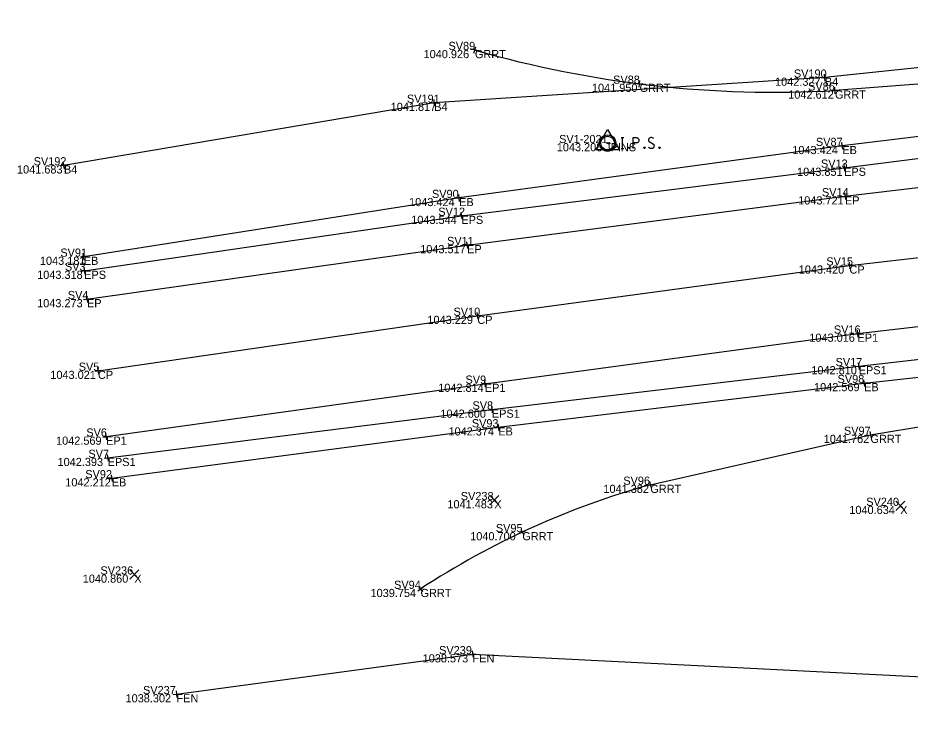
# Model space of a CAD drawing. Extents: x 1542529 to 1609210, y 587215 to 645373.
# Drawn here: x 1608659.8 to 1608791, y 645167.7 to 645271.5 of the extents above; entities that cross this region are included whole.
import ezdxf

# ---------------------------------------------------------------- set-up
doc = ezdxf.new("R2010")
doc.units = 0
for name, color, linetype in [('PV_X_COP', 7, 'Continuous'), ('PV_X_EOP', 7, 'Continuous'), ('PV_X_Shoulder', 7, 'Continuous'), ('PV_X_Shoulder_Aggregate', 7, 'Continuous'), ('RD_X_Fence', 7, 'Continuous'), ('RD_X_GR_Rt', 7, 'Continuous'), ('SV_Control_Point', 7, 'Continuous'), ('SV_P_Mon_Cells_Set', 7, 'Continuous'), ('SV_X_Break_Lines', 7, 'Continuous'), ('SV_X_Random_Point', 7, 'Continuous'), ('SV_X_Shot_Marker', 7, 'Continuous'), ('SV_X_Text_Comment', 7, 'Continuous'), ('SV_X_Text_Elevation', 7, 'Continuous'), ('SV_X_Text_Name', 7, 'Continuous')]:
    doc.layers.add(name, color=color, linetype=linetype)

msp = doc.modelspace()

# ---------------------------------------------------------------- linework, layer by layer
at = {"layer": 'PV_X_COP'}
msp.add_lwpolyline([(1608671.55, 645219.6), (1608727.32, 645227.68), (1608782.03, 645235.07), (1608837.47, 645241.45), (1608884.55, 645247.04)], dxfattribs=at)
at = {"layer": 'PV_X_EOP'}
for points in [[(1608669.93, 645230.13), (1608725.82, 645238.07), (1608781.37, 645245.23), (1608836.27, 645251.75), (1608887.49, 645257.66)], [(1608672.74, 645209.93), (1608728.42, 645217.7), (1608783.22, 645225.06), (1608838.86, 645231.47), (1608881.41, 645236.41)]]:
    msp.add_lwpolyline(points, dxfattribs=at)
at = {"layer": 'PV_X_Shoulder'}
for points in [[(1608669.52, 645234.3), (1608724.97, 645242.37), (1608781.24, 645249.44), (1608835.57, 645256.3), (1608888.53, 645262.28)], [(1608672.97, 645206.8), (1608729.46, 645213.9), (1608783.39, 645220.28), (1608840.72, 645226.83), (1608879.25, 645231.61)]]:
    msp.add_lwpolyline(points, dxfattribs=at)
at = {"layer": 'PV_X_Shoulder_Aggregate'}
for points in [[(1608884.62, 645267.54), (1608835.11, 645259.22), (1608780.98, 645252.63), (1608724.64, 645244.99), (1608669.45, 645236.36)], [(1608673.57, 645203.81), (1608730.4, 645211.29), (1608784.18, 645217.8), (1608839.95, 645223.89), (1608878.18, 645228.32)]]:
    msp.add_lwpolyline(points, dxfattribs=at)
at = {"layer": 'RD_X_Fence'}
msp.add_lwpolyline([(1608683.09, 645172.08), (1608726.62, 645177.95), (1608798.6, 645174.35), (1608837.85, 645170.02), (1608869.08, 645167.68)], dxfattribs=at)
at = {"layer": 'RD_X_GR_Rt'}
for p, q in [((1608834.71, 645264.92), (1608779.9, 645260.78)), ((1608785.12, 645210.19), (1608840.67, 645219.49)), ((1608752.75, 645202.85), (1608785.12, 645210.19))]:
    msp.add_line(p, q, dxfattribs=at)
for centre, radius, start, end in [((1608771, 645420.11), 159.58, 253.98, 273.1961), ((1608785.29, 645086.07), 121.23, 105.5726, 123.169)]:
    msp.add_arc(centre, radius, start, end, dxfattribs=at)
at = {"layer": 'SV_Control_Point'}
for p, q in [((1608744.74, 645252.05), (1608746.47, 645255.05)), ((1608746.47, 645255.05), (1608748.21, 645252.05)), ((1608746.47, 645253.05), (1608746.47, 645253.05)), ((1608748.21, 645252.05), (1608744.74, 645252.05))]:
    msp.add_line(p, q, dxfattribs=at)
msp.add_circle((1608746.47, 645253.05), 1, dxfattribs=at)
at = {"layer": 'SV_P_Mon_Cells_Set'}
for points in [[(1608746.57, 645253.09), (1608746.59, 645253.09)], [(1608746.57, 645253.01), (1608746.59, 645253.01)], [(1608746.58, 645253.01), (1608746.58, 645253.09)], [(1608746.63, 645253.02), (1608746.63, 645253.02), (1608746.64, 645253.02), (1608746.64, 645253.02), (1608746.64, 645253.02), (1608746.64, 645253.01), (1608746.63, 645253.01), (1608746.63, 645253.01), (1608746.63, 645253.01), (1608746.63, 645253.02), (1608746.63, 645253.02), (1608746.63, 645253.02), (1608746.63, 645253.02)], [(1608746.66, 645253.01), (1608746.66, 645253.09), (1608746.69, 645253.09), (1608746.69, 645253.09), (1608746.69, 645253.09), (1608746.7, 645253.09), (1608746.7, 645253.09), (1608746.7, 645253.08), (1608746.7, 645253.08), (1608746.7, 645253.08), (1608746.7, 645253.07), (1608746.7, 645253.07), (1608746.7, 645253.06), (1608746.7, 645253.06), (1608746.7, 645253.06), (1608746.69, 645253.05), (1608746.69, 645253.05), (1608746.69, 645253.05), (1608746.66, 645253.05)], [(1608746.74, 645253.02), (1608746.75, 645253.02), (1608746.75, 645253.02), (1608746.75, 645253.02), (1608746.75, 645253.02), (1608746.75, 645253.01), (1608746.75, 645253.01), (1608746.74, 645253.01), (1608746.74, 645253.01), (1608746.74, 645253.02), (1608746.74, 645253.02), (1608746.74, 645253.02), (1608746.74, 645253.02)], [(1608746.81, 645253.09), (1608746.81, 645253.09), (1608746.81, 645253.09), (1608746.8, 645253.09), (1608746.8, 645253.09), (1608746.79, 645253.09), (1608746.79, 645253.09), (1608746.78, 645253.09), (1608746.78, 645253.09), (1608746.77, 645253.08), (1608746.77, 645253.08), (1608746.77, 645253.07), (1608746.77, 645253.07), (1608746.78, 645253.06), (1608746.81, 645253.04), (1608746.81, 645253.04), (1608746.81, 645253.04), (1608746.81, 645253.04), (1608746.81, 645253.03), (1608746.81, 645253.03), (1608746.81, 645253.03), (1608746.81, 645253.02), (1608746.81, 645253.02), (1608746.81, 645253.02), (1608746.81, 645253.02), (1608746.81, 645253.01), (1608746.8, 645253.01), (1608746.8, 645253.01), (1608746.8, 645253.01), (1608746.79, 645253.01), (1608746.79, 645253.01), (1608746.78, 645253.02), (1608746.77, 645253.02)], [(1608746.85, 645253.02), (1608746.86, 645253.02), (1608746.86, 645253.02), (1608746.86, 645253.02), (1608746.86, 645253.02), (1608746.86, 645253.01), (1608746.86, 645253.01), (1608746.85, 645253.01), (1608746.85, 645253.01), (1608746.85, 645253.02), (1608746.85, 645253.02), (1608746.85, 645253.02), (1608746.85, 645253.02)], [(1608748.49, 645253.85), (1608748.84, 645253.85)], [(1608748.67, 645252.25), (1608748.67, 645253.85)], [(1608750.23, 645252.25), (1608750.23, 645253.85), (1608750.76, 645253.85), (1608750.82, 645253.84), (1608750.89, 645253.82), (1608750.93, 645253.79), (1608750.96, 645253.77), (1608751.01, 645253.7), (1608751.04, 645253.64), (1608751.06, 645253.54), (1608751.06, 645253.39), (1608751.05, 645253.34), (1608751.03, 645253.26), (1608750.98, 645253.17), (1608750.94, 645253.14), (1608750.91, 645253.11), (1608750.85, 645253.09), (1608750.76, 645253.07), (1608750.23, 645253.07)], [(1608753.24, 645253.74), (1608753.22, 645253.77), (1608753.19, 645253.79), (1608753.09, 645253.83), (1608752.97, 645253.85), (1608752.88, 645253.85), (1608752.85, 645253.85), (1608752.7, 645253.82), (1608752.58, 645253.74), (1608752.5, 645253.64), (1608752.48, 645253.54), (1608752.48, 645253.46), (1608752.5, 645253.36), (1608752.59, 645253.27), (1608753.2, 645252.9), (1608753.25, 645252.85), (1608753.28, 645252.8), (1608753.3, 645252.72), (1608753.3, 645252.64), (1608753.29, 645252.57), (1608753.28, 645252.52), (1608753.25, 645252.46), (1608753.23, 645252.4), (1608753.21, 645252.37), (1608753.18, 645252.33), (1608753.14, 645252.3), (1608753.1, 645252.28), (1608753.07, 645252.27), (1608752.97, 645252.25), (1608752.81, 645252.25), (1608752.71, 645252.28), (1608752.57, 645252.37), (1608752.48, 645252.44)], [(1608748.49, 645252.25), (1608748.84, 645252.25)], [(1608749.63, 645252.47), (1608749.68, 645252.47), (1608749.72, 645252.44), (1608749.75, 645252.39), (1608749.75, 645252.33), (1608749.72, 645252.28), (1608749.68, 645252.25), (1608749.63, 645252.25), (1608749.59, 645252.28), (1608749.56, 645252.33), (1608749.56, 645252.39), (1608749.59, 645252.44), (1608749.63, 645252.47)], [(1608751.88, 645252.47), (1608751.93, 645252.47), (1608751.96, 645252.44), (1608752, 645252.39), (1608752, 645252.33), (1608751.96, 645252.28), (1608751.93, 645252.25), (1608751.88, 645252.25), (1608751.84, 645252.28), (1608751.81, 645252.33), (1608751.81, 645252.39), (1608751.84, 645252.44), (1608751.88, 645252.47)], [(1608754.06, 645252.47), (1608754.11, 645252.47), (1608754.15, 645252.44), (1608754.18, 645252.39), (1608754.18, 645252.33), (1608754.15, 645252.28), (1608754.11, 645252.25), (1608754.06, 645252.25), (1608754.03, 645252.28), (1608753.99, 645252.33), (1608753.99, 645252.39), (1608754.03, 645252.44), (1608754.06, 645252.47)]]:
    msp.add_lwpolyline(points, dxfattribs=at)
for radius in [1.2, 0.06]:
    msp.add_circle((1608746.47, 645253.05), radius, dxfattribs=at)
at = {"layer": 'SV_X_Break_Lines'}
msp.add_lwpolyline([(1608884.15, 645271.45), (1608835, 645268.59), (1608778.42, 645262.67), (1608720.98, 645258.97), (1608666.54, 645249.78)], dxfattribs=at)
at = {"layer": 'SV_X_Random_Point'}
for p, q in [((1608729.14, 645199.92), (1608730.48, 645201.26)), ((1608729.14, 645201.26), (1608730.48, 645199.92)), ((1608788.84, 645199.09), (1608790.17, 645200.42)), ((1608788.84, 645200.42), (1608790.17, 645199.09)), ((1608676.23, 645188.99), (1608677.56, 645190.33)), ((1608676.23, 645190.33), (1608677.56, 645188.99))]:
    msp.add_line(p, q, dxfattribs=at)
at = {"layer": 'SV_X_Shot_Marker'}
for p, q in [((1608726.82, 645266.25), (1608727.1, 645267.21)), ((1608727.44, 645266.59), (1608726.48, 645266.86)), ((1608726.96, 645266.73), (1608726.96, 645266.73)), ((1608751.11, 645261.27), (1608751.23, 645262.26)), ((1608778.92, 645262.72), (1608777.92, 645262.61)), ((1608778.47, 645262.17), (1608778.37, 645263.16)), ((1608778.42, 645262.67), (1608778.42, 645262.67)), ((1608751.67, 645261.7), (1608750.67, 645261.83)), ((1608751.17, 645261.77), (1608751.17, 645261.77)), ((1608780.4, 645260.8), (1608779.4, 645260.75)), ((1608779.93, 645260.28), (1608779.87, 645261.28)), ((1608779.9, 645260.78), (1608779.9, 645260.78)), ((1608721.01, 645258.47), (1608720.95, 645259.47)), ((1608721.48, 645259), (1608720.48, 645258.94)), ((1608720.98, 645258.97), (1608720.98, 645258.97)), ((1608781.47, 645252.69), (1608780.48, 645252.57)), ((1608781.04, 645252.14), (1608780.92, 645253.13)), ((1608780.98, 645252.63), (1608780.98, 645252.63)), ((1608666.62, 645249.29), (1608666.45, 645250.28)), ((1608667.03, 645249.87), (1608666.04, 645249.7)), ((1608666.54, 645249.78), (1608666.54, 645249.78)), ((1608780.75, 645249.38), (1608781.74, 645249.5)), ((1608781.18, 645249.94), (1608781.31, 645248.94)), ((1608781.24, 645249.44), (1608781.24, 645249.44)), ((1608725.14, 645245.05), (1608724.15, 645244.92)), ((1608724.71, 645244.49), (1608724.58, 645245.48)), ((1608724.64, 645244.99), (1608724.64, 645244.99)), ((1608780.88, 645245.17), (1608781.87, 645245.29)), ((1608781.31, 645245.73), (1608781.44, 645244.74)), ((1608781.37, 645245.23), (1608781.37, 645245.23)), ((1608724.47, 645242.3), (1608725.46, 645242.45)), ((1608724.9, 645242.87), (1608725.04, 645241.88)), ((1608724.97, 645242.37), (1608724.97, 645242.37)), ((1608725.75, 645238.56), (1608725.89, 645237.57)), ((1608725.32, 645238), (1608726.31, 645238.14)), ((1608725.82, 645238.07), (1608725.82, 645238.07)), ((1608669.95, 645236.44), (1608668.96, 645236.29)), ((1608669.53, 645235.87), (1608669.38, 645236.86)), ((1608669.45, 645236.36), (1608669.45, 645236.36)), ((1608669.03, 645234.23), (1608670.02, 645234.38)), ((1608669.45, 645234.8), (1608669.59, 645233.81)), ((1608781.54, 645235), (1608782.53, 645235.14)), ((1608781.97, 645235.56), (1608782.1, 645234.57)), ((1608782.03, 645235.07), (1608782.03, 645235.07)), ((1608669.52, 645234.3), (1608669.52, 645234.3)), ((1608669.86, 645230.62), (1608670, 645229.63)), ((1608669.44, 645230.06), (1608670.43, 645230.2)), ((1608669.93, 645230.13), (1608669.93, 645230.13)), ((1608727.25, 645228.17), (1608727.4, 645227.19)), ((1608726.83, 645227.61), (1608727.82, 645227.75)), ((1608727.32, 645227.68), (1608727.32, 645227.68)), ((1608783.15, 645225.55), (1608783.28, 645224.56)), ((1608782.72, 645224.99), (1608783.71, 645225.12)), ((1608783.22, 645225.06), (1608783.22, 645225.06)), ((1608671.48, 645220.09), (1608671.63, 645219.1)), ((1608782.89, 645220.22), (1608783.88, 645220.33)), ((1608783.33, 645220.77), (1608783.45, 645219.78)), ((1608783.39, 645220.28), (1608783.39, 645220.28)), ((1608671.06, 645219.52), (1608672.05, 645219.67)), ((1608671.55, 645219.6), (1608671.55, 645219.6)), ((1608727.93, 645217.63), (1608728.92, 645217.77)), ((1608728.35, 645218.19), (1608728.49, 645217.2)), ((1608728.42, 645217.7), (1608728.42, 645217.7)), ((1608783.68, 645217.73), (1608784.68, 645217.86)), ((1608784.12, 645218.29), (1608784.24, 645217.3)), ((1608784.18, 645217.8), (1608784.18, 645217.8)), ((1608728.96, 645213.83), (1608729.95, 645213.96)), ((1608729.39, 645214.39), (1608729.52, 645213.4)), ((1608729.46, 645213.9), (1608729.46, 645213.9)), ((1608729.91, 645211.22), (1608730.9, 645211.35)), ((1608730.34, 645211.78), (1608730.47, 645210.79)), ((1608730.4, 645211.29), (1608730.4, 645211.29)), ((1608672.25, 645209.86), (1608673.24, 645210)), ((1608672.67, 645210.42), (1608672.81, 645209.43)), ((1608672.74, 645209.93), (1608672.74, 645209.93)), ((1608784.62, 645210.11), (1608785.61, 645210.27)), ((1608785.03, 645210.69), (1608785.2, 645209.7)), ((1608785.12, 645210.19), (1608785.12, 645210.19)), ((1608672.48, 645206.74), (1608673.47, 645206.86)), ((1608672.91, 645207.3), (1608673.04, 645206.31)), ((1608672.97, 645206.8), (1608672.97, 645206.8)), ((1608673.5, 645204.3), (1608673.63, 645203.31)), ((1608673.07, 645203.74), (1608674.06, 645203.87)), ((1608673.57, 645203.81), (1608673.57, 645203.81)), ((1608752.26, 645202.74), (1608753.23, 645202.96)), ((1608752.64, 645203.34), (1608752.86, 645202.37)), ((1608752.75, 645202.85), (1608752.75, 645202.85)), ((1608733.72, 645196.34), (1608734.14, 645195.43)), ((1608733.48, 645195.67), (1608734.38, 645196.1)), ((1608733.93, 645195.89), (1608733.93, 645195.89)), ((1608718.55, 645187.28), (1608719.38, 645187.82)), ((1608718.69, 645187.97), (1608719.24, 645187.13)), ((1608718.97, 645187.55), (1608718.97, 645187.55)), ((1608726.13, 645177.88), (1608727.12, 645178.02)), ((1608726.56, 645178.44), (1608726.69, 645177.45)), ((1608726.62, 645177.95), (1608726.62, 645177.95)), ((1608682.59, 645172.01), (1608683.58, 645172.14)), ((1608683.02, 645172.57), (1608683.15, 645171.58)), ((1608683.09, 645172.08), (1608683.09, 645172.08))]:
    msp.add_line(p, q, dxfattribs=at)

# ---------------------------------------------------------------- texts
at = {"layer": 'SV_X_Text_Comment'}
for s, p in [('GRRT', (1608726.96, 645265.53)), ('B4', (1608778.42, 645261.47)), ('GRRT', (1608751.17, 645260.57)), ('GRRT', (1608779.9, 645259.58)), ('B4', (1608720.98, 645257.77)), ('IPINS', (1608746.47, 645251.85)), ('EB', (1608780.98, 645251.43)), ('B4', (1608666.54, 645248.58)), ('EPS', (1608781.24, 645248.24)), ('EB', (1608724.64, 645243.79)), ('EP', (1608781.37, 645244.03)), ('EPS', (1608724.97, 645241.17)), ('EP', (1608725.82, 645236.87)), ('EB', (1608669.45, 645235.16)), ('CP', (1608782.03, 645233.87)), ('EPS', (1608669.52, 645233.1)), ('EP', (1608669.93, 645228.93)), ('CP', (1608727.32, 645226.48)), ('EP1', (1608783.22, 645223.86)), ('EPS1', (1608783.39, 645219.08)), ('CP', (1608671.55, 645218.4)), ('EP1', (1608728.42, 645216.5)), ('EB', (1608784.18, 645216.6)), ('EPS1', (1608729.46, 645212.7)), ('EB', (1608730.4, 645210.09)), ('EP1', (1608672.74, 645208.73)), ('GRRT', (1608785.12, 645208.99)), ('EPS1', (1608672.97, 645205.6)), ('EB', (1608673.57, 645202.61)), ('GRRT', (1608752.75, 645201.65)), ('X', (1608729.81, 645199.39)), ('X', (1608789.5, 645198.55)), ('GRRT', (1608733.93, 645194.69)), ('X', (1608676.89, 645188.46)), ('GRRT', (1608718.97, 645186.35)), ('FEN', (1608726.62, 645176.75)), ('FEN', (1608683.09, 645170.88))]:
    msp.add_text(s, height=1.2, dxfattribs=at).set_placement(p)
at = {"layer": 'SV_X_Text_Elevation'}
for s, height, p in [('1040.926', 1.2, (1608719.42, 645265.53)), ('1042.327', 1.2, (1608771.09, 645261.47)), ('1041.950', 1.2, (1608744.17, 645260.57)), ('1042.612', 1.2, (1608773.03, 645259.58)), ('1041.817', 1.2, (1608714.58, 645257.77)), ('1043.208', 1.2, (1608739, 645251.85)), ('1043.21', 0.06, (1608746.18, 645252.99)), ('1043.424', 1.2, (1608773.63, 645251.43)), ('1041.683', 1.2, (1608659.64, 645248.58)), ('1043.851', 1.2, (1608774.33, 645248.24)), ('1043.424', 1.2, (1608717.29, 645243.79)), ('1043.721', 1.2, (1608774.49, 645244.03)), ('1043.544', 1.2, (1608717.6, 645241.17)), ('1043.517', 1.2, (1608718.92, 645236.87)), ('1043.181', 1.2, (1608663.01, 645235.16)), ('1043.420', 1.2, (1608774.57, 645233.87)), ('1043.318', 1.2, (1608662.6, 645233.1)), ('1043.273', 1.2, (1608662.6, 645228.93)), ('1043.229', 1.2, (1608719.98, 645226.48)), ('1043.016', 1.2, (1608776.13, 645223.86)), ('1042.810', 1.2, (1608776.43, 645219.08)), ('1043.021', 1.2, (1608664.54, 645218.4)), ('1042.814', 1.2, (1608721.57, 645216.5)), ('1042.569', 1.2, (1608776.82, 645216.6)), ('1042.600', 1.2, (1608721.89, 645212.7)), ('1042.374', 1.2, (1608723.08, 645210.09)), ('1042.569', 1.2, (1608665.38, 645208.73)), ('1041.762', 1.2, (1608778.25, 645208.99)), ('1042.393', 1.2, (1608665.6, 645205.6)), ('1042.212', 1.2, (1608666.74, 645202.61)), ('1041.382', 1.2, (1608745.86, 645201.65)), ('1041.483', 1.2, (1608722.92, 645199.39)), ('1040.634', 1.2, (1608782.01, 645198.55)), ('1040.700', 1.2, (1608726.27, 645194.69)), ('1040.860', 1.2, (1608669.31, 645188.46)), ('1039.754', 1.2, (1608711.62, 645186.35)), ('1038.573', 1.2, (1608719.28, 645176.75)), ('1038.302', 1.2, (1608675.6, 645170.88))]:
    msp.add_text(s, height=height, dxfattribs=at).set_placement(p)
at = {"layer": 'SV_X_Text_Name'}
for s, height, p in [('SV89', 1.2, (1608723.08, 645266.73)), ('SV190', 1.2, (1608773.86, 645262.67)), ('SV88', 1.2, (1608747.29, 645261.77)), ('SV86', 1.2, (1608775.95, 645260.78)), ('SV191', 1.2, (1608716.97, 645258.97)), ('SV1-2021', 1.2, (1608739.34, 645253.05)), ('SV12021', 0.06, (1608746.17, 645253.05)), ('SV87', 1.2, (1608777.1, 645252.63)), ('SV192', 1.2, (1608662.09, 645249.78)), ('SV13', 1.2, (1608777.84, 645249.44)), ('SV90', 1.2, (1608720.65, 645244.99)), ('SV14', 1.2, (1608777.98, 645245.23)), ('SV12', 1.2, (1608721.58, 645242.37)), ('SV11', 1.2, (1608722.87, 645238.07)), ('SV91', 1.2, (1608666.01, 645236.36)), ('SV15', 1.2, (1608778.63, 645235.07)), ('SV3', 1.2, (1608666.69, 645234.3)), ('SV4', 1.2, (1608667.11, 645230.13)), ('SV10', 1.2, (1608723.82, 645227.68)), ('SV16', 1.2, (1608779.74, 645225.06)), ('SV17', 1.2, (1608779.99, 645220.28)), ('SV5', 1.2, (1608668.72, 645219.6)), ('SV9', 1.2, (1608725.58, 645217.7)), ('SV98', 1.2, (1608780.28, 645217.8)), ('SV8', 1.2, (1608726.61, 645213.9)), ('SV93', 1.2, (1608726.51, 645211.29)), ('SV6', 1.2, (1608669.83, 645209.93)), ('SV97', 1.2, (1608781.22, 645210.19)), ('SV7', 1.2, (1608670.14, 645206.8)), ('SV92', 1.2, (1608669.68, 645203.81)), ('SV96', 1.2, (1608748.78, 645202.85)), ('SV238', 1.2, (1608724.89, 645200.59)), ('SV240', 1.2, (1608784.5, 645199.75)), ('SV95', 1.2, (1608730.04, 645195.89)), ('SV236', 1.2, (1608671.91, 645189.66)), ('SV94', 1.2, (1608715.08, 645187.55)), ('SV239', 1.2, (1608721.7, 645177.95)), ('SV237', 1.2, (1608678.17, 645172.08))]:
    msp.add_text(s, height=height, dxfattribs=at).set_placement(p)

doc.saveas('drawing.dxf')
